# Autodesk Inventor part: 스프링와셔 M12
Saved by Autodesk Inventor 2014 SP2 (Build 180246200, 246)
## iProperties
Created: 2024-04
Part Number: 스프링와셔 M12
Material: Generic
Document SubType Name: Modeling
Designer: Administrator
Density: 1 g/cm^3
Appearance: Default
Author: Administrator
Author: jhkim
Description: 스프링 잠금 와셔
Creation Date: 2024-04-08
Sending System: Autodesk Inventor 2025
Preprocessor: ST-DEVELOPER v20
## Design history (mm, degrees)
node "스프링와셔 M121"
body "Solid1"
node "기준1"
